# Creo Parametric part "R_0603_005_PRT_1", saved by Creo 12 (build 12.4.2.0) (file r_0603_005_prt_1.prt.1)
Units: Custom; MM, KILOGRAM, SECS

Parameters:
  PTC_WM_ITERATION = "0"
  PTC_WM_VERSION = "-.0"
  PTC_WM_LIFECYCLE_STATE = "In Work"
  PTC_WM_LIFECYCLE = "MO_CADDocument"
  PTC_WM_CREATED_BY = "Maximilian Roepper (Z0017RMS: MO)"
  PTC_WM_CREATED_ON = "18-Sep-26 11:36:42 AM"
  PTC_WM_MODIFIED_BY = "Maximilian Roepper (Z0017RMS: MO)"
  PTC_WM_MODIFIED_ON = "18-Sep-26 11:36:46 AM"
  PDMLINKNUMBER = "PDM000071455342"
  PTC_WM_NAME = "r_0603_005_prt_1.prt"
  PTC_WM_NUMBER = "PDM000071455342"

Other parameters: WEIGHT, WEIGHT_FACTOR, WEIGHT_ADD, _MASS_TEMP, _DIFF_TEMP, MC_ERRORS, SUPPLIER

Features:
  1. coordinate system
  2. datum plane "PRT_YZ"
  3. datum plane "PRT_XY"
  4. datum plane "PRT_XZ"
  5. coordinate system
  6. datum axis
  7. datum axis
  8. datum axis
  9. coordinate system
  10. imported feature
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
Other named items: PRT, SIEMENS_MO, DRW_VIEW_ORG, PRT_X, PRT_Y, PRT_Z, CS0, ROUGH_GROB

Layers: 00_STD_CSYS-KSYS, 01_STD_PLANES-EBENEN, 02_STD_AXES-ACHSEN, 03_STD_CSYS-KSYS, 24_IMPORT_FEAT-IMPORT_KE

Surfaces: 18 plane, 8 cylinder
